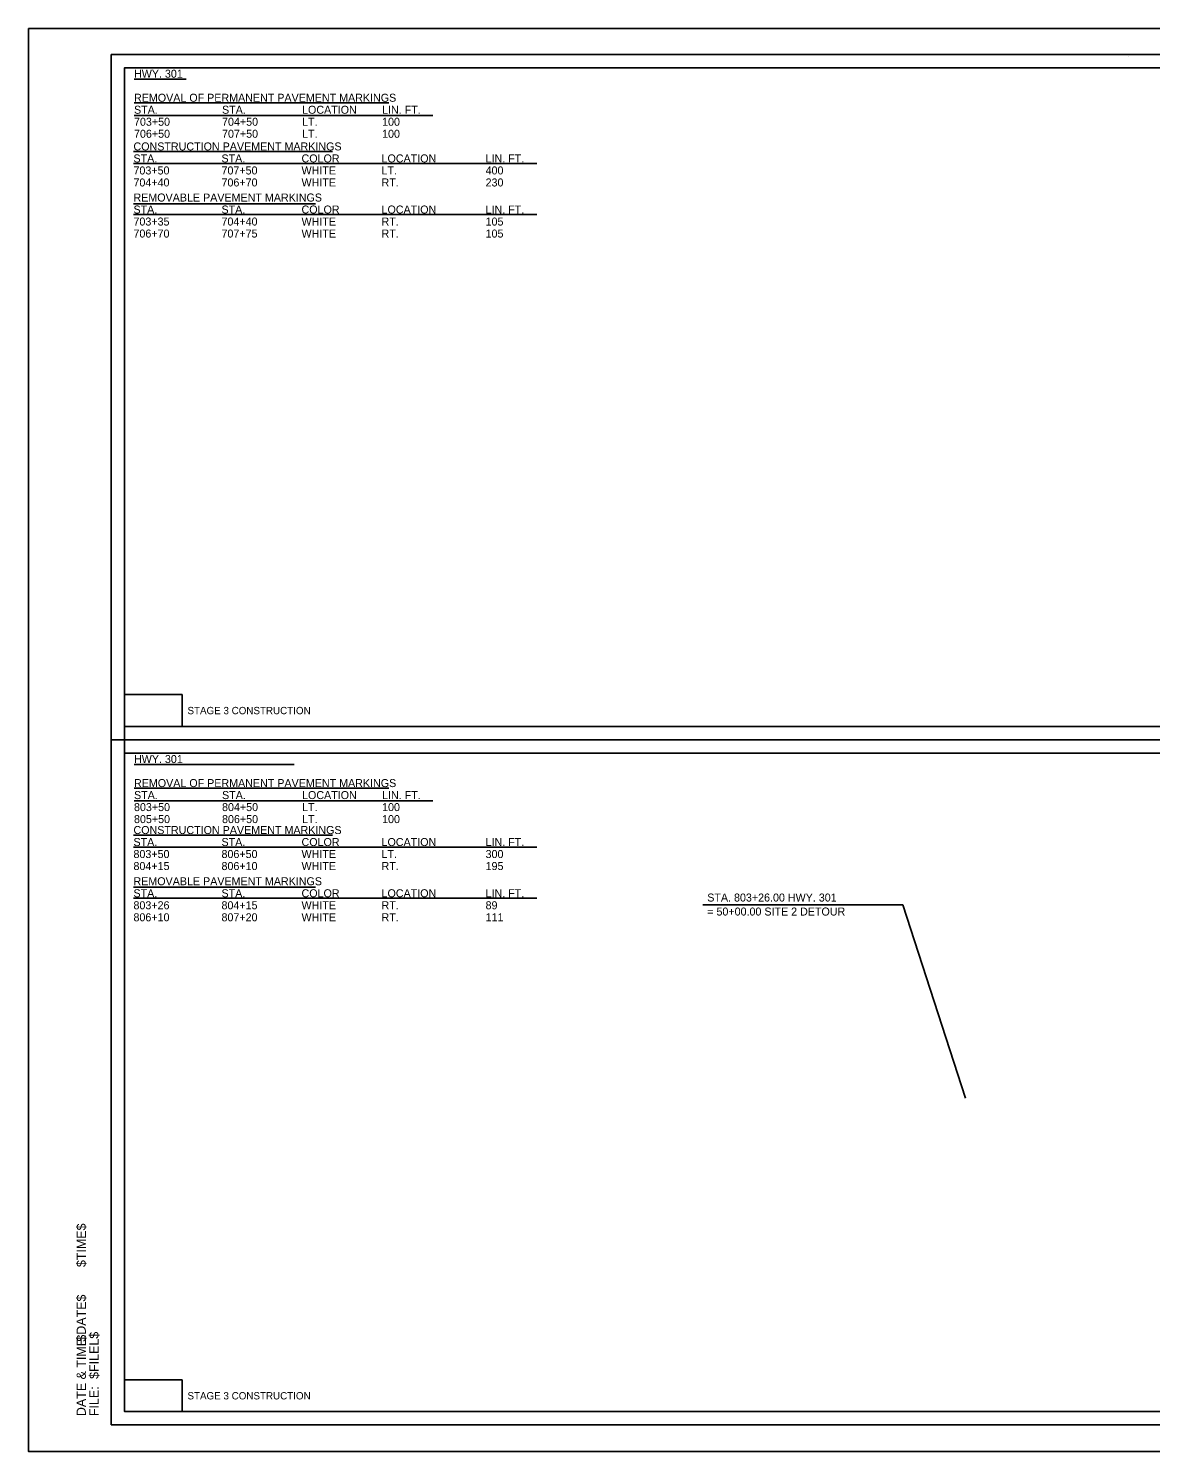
# Model space of a CAD drawing. Extents: x 1368648 to 1927880, y -1037443 to 380209.
# Drawn here: x 1377930 to 1378771, y 378686 to 379753 of the extents above; entities that cross this region are included whole.
import ezdxf

# ---------------------------------------------------------------- set-up
doc = ezdxf.new("R2010")
doc.units = 0
for name, color, linetype in [('Default', 7, 'Continuous'), ('R_Border', 7, 'Continuous'), ('R_Border Notes', 7, 'Continuous'), ('R_Detour Annot Limits', 7, 'Continuous'), ('R_No Plot', 7, 'Continuous')]:
    doc.layers.add(name, color=color, linetype=linetype)

msp = doc.modelspace()

# ---------------------------------------------------------------- linework, layer by layer
at = {"layer": 'Default'}
for p, q in [((1378009.2, 379714.7), (1378048.2, 379714.7)), ((1378009.2, 379696.9), (1378200.2, 379696.9)), ((1378009.2, 379687.5), (1378233.2, 379687.5)), ((1378008.9, 379660.4), (1378158, 379660.4)), ((1378008.9, 379651.4), (1378311.1, 379651.4)), ((1378008.9, 379621.4), (1378145.3, 379621.4)), ((1378008.9, 379613.2), (1378311.1, 379613.2)), ((1378009.2, 379201), (1378129.2, 379201)), ((1378009.2, 379183.2), (1378200.2, 379183.2)), ((1378009.2, 379173.9), (1378233.2, 379173.9)), ((1378008.9, 379148), (1378158, 379148)), ((1378008.9, 379139), (1378311.1, 379139)), ((1378008.9, 379109), (1378145.3, 379109)), ((1378008.9, 379100.8), (1378311.1, 379100.8))]:
    msp.add_line(p, q, dxfattribs=at)
for points in [[(1378002.1, 379229.6), (1378045.2, 379229.6), (1378045.2, 379253.4), (1378002.1, 379253.4), (1378002.1, 379229.6)], [(1378002.1, 378716), (1378045.2, 378716), (1378045.2, 378739.7), (1378002.1, 378739.7), (1378002.1, 378716)]]:
    msp.add_lwpolyline(points, dxfattribs=at)
at = {"layer": 'R_Border'}
for p, q in [((1377992.1, 379733.3), (1379573, 379733.3)), ((1377992.1, 378706), (1377992.1, 379733.3)), ((1378754.7, 379732), (1378754.7, 379732)), ((1378754.7, 379732), (1378754.7, 379732)), ((1379573, 379219.6), (1377992.1, 379219.6)), ((1377992.1, 378706), (1377992.1, 378706)), ((1379573, 378706), (1377992.1, 378706))]:
    msp.add_line(p, q, dxfattribs=at)
at = {"layer": 'R_Detour Annot Limits'}
msp.add_lwpolyline([(1378435.6, 379095.8), (1378585.6, 379095.8), (1378632.6, 378950.9)], dxfattribs=at)
at = {"layer": 'R_No Plot'}
for points in [[(1377930.1, 379752.7), (1379596.8, 379752.7), (1379596.8, 378686), (1377930.1, 378686)], [(1379563, 379229.6), (1378002.1, 379229.6), (1378002.1, 379723.3), (1379249.8, 379723.3), (1379249.8, 379673.9), (1379337.5, 379673.9), (1379458, 379673.9), (1379458, 379562.2), (1379563, 379562.2)], [(1379563, 379229.6), (1378002.1, 379229.6), (1378002.1, 379723.3), (1379249.8, 379723.3), (1379249.8, 379673.9), (1379337.5, 379673.9), (1379458, 379673.9), (1379458, 379562.2), (1379563, 379562.2)], [(1379563, 379229.6), (1378002.1, 379229.6), (1378002.1, 379723.3), (1379249.8, 379723.3), (1379249.8, 379673.9), (1379337.5, 379673.9), (1379458, 379673.9), (1379458, 379562.2), (1379563, 379562.2)], [(1379563, 379229.6), (1378002.1, 379229.6), (1378002.1, 379723.3), (1379249.8, 379723.3), (1379249.8, 379673.9), (1379337.5, 379673.9), (1379458, 379673.9), (1379458, 379562.2), (1379563, 379562.2)], [(1379563, 379229.6), (1378002.1, 379229.6), (1378002.1, 379723.3), (1379249.8, 379723.3), (1379249.8, 379673.9), (1379337.5, 379673.9), (1379458, 379673.9), (1379458, 379562.2), (1379563, 379562.2)], [(1379563, 379229.6), (1378002.1, 379229.6), (1378002.1, 379723.3), (1379249.8, 379723.3), (1379249.8, 379673.9), (1379337.5, 379673.9), (1379458, 379673.9), (1379458, 379562.2), (1379563, 379562.2)], [(1379563, 379229.6), (1378002.1, 379229.6), (1378002.1, 379723.3), (1379249.8, 379723.3), (1379249.8, 379673.9), (1379337.5, 379673.9), (1379458, 379673.9), (1379458, 379562.2), (1379563, 379562.2)], [(1378002.1, 379723.3), (1379249.8, 379723.3), (1379249.8, 379673.9), (1379337.5, 379673.9), (1379458, 379673.9), (1379458, 379562.2), (1379563, 379562.2), (1379563, 378716), (1378002.1, 378716)], [(1378002.1, 379209.6), (1379563, 379209.6), (1379563, 378716), (1378002.1, 378716)], [(1378002.1, 379209.6), (1379563, 379209.6), (1379563, 378716), (1378002.1, 378716)], [(1378002.1, 379209.6), (1379563, 379209.6), (1379563, 378716), (1378002.1, 378716)], [(1378002.1, 379209.6), (1379563, 379209.6), (1379563, 378716), (1378002.1, 378716)], [(1378002.1, 379209.6), (1379563, 379209.6), (1379563, 378716), (1378002.1, 378716)], [(1378002.1, 379209.6), (1379563, 379209.6), (1379563, 378716), (1378002.1, 378716)], [(1378002.1, 379209.6), (1379563, 379209.6), (1379563, 378716), (1378002.1, 378716)]]:
    msp.add_lwpolyline(points, close=True, dxfattribs=at)

# ---------------------------------------------------------------- texts
at = {"layer": 'Default'}
for s, height, p in [('HWY. 301 ', 6, (1378009.2, 379715.8)), ('REMOVAL OF PERMANENT PAVEMENT MARKINGS', 6, (1378009.2, 379697.8)), ('STA.', 6, (1378009.2, 379688.8)), ('STA.', 6, (1378075.2, 379688.8)), ('LOCATION', 6, (1378135.2, 379688.8)), ('LIN. FT.', 6, (1378195.2, 379688.8)), ('703+50 ', 6, (1378009.2, 379679.8)), ('704+50', 6, (1378075.2, 379679.8)), ('LT.', 6, (1378135.2, 379679.8)), ('100', 6, (1378195.2, 379679.8)), ('CONSTRUCTION PAVEMENT MARKINGS', 6, (1378008.8, 379661.3)), ('706+50', 6, (1378009.2, 379670.8)), ('707+50', 6, (1378075.2, 379670.8)), ('LT.', 6, (1378135.2, 379670.8)), ('100', 6, (1378195.2, 379670.8)), ('STA.', 6, (1378008.8, 379652.3)), ('STA.', 6, (1378074.8, 379652.3)), ('COLOR', 6, (1378134.8, 379652.3)), ('LOCATION', 6, (1378194.8, 379652.3)), ('LIN. FT.', 6, (1378272.8, 379652.3)), ('703+50', 6, (1378008.8, 379643.3)), ('707+50', 6, (1378074.8, 379643.3)), ('WHITE', 6, (1378134.8, 379643.3)), ('LT.', 6, (1378194.8, 379643.3)), ('400', 6, (1378272.8, 379643.3)), ('704+40', 6, (1378008.8, 379634.3)), ('706+70', 6, (1378074.8, 379634.3)), ('WHITE', 6, (1378134.8, 379634.3)), ('RT.', 6, (1378194.8, 379634.3)), ('230', 6, (1378272.8, 379634.3)), ('REMOVABLE PAVEMENT MARKINGS', 6, (1378008.8, 379623)), ('STA.', 6, (1378008.8, 379614)), ('STA.', 6, (1378074.8, 379614)), ('COLOR', 6, (1378134.8, 379614)), ('LOCATION', 6, (1378194.8, 379614)), ('LIN. FT.', 6, (1378272.8, 379614)), ('703+35', 6, (1378008.8, 379605)), ('704+40', 6, (1378074.8, 379605)), ('WHITE', 6, (1378134.8, 379605)), ('RT.', 6, (1378194.8, 379605)), ('105', 6, (1378272.8, 379605)), ('706+70', 6, (1378008.8, 379596)), ('707+75', 6, (1378074.8, 379596)), ('WHITE', 6, (1378134.8, 379596)), ('RT.', 6, (1378194.8, 379596)), ('105', 6, (1378272.8, 379596)), ('  STAGE 3 CONSTRUCTION', 5.5, (1378045.2, 379238.7)), ('HWY. 301 ', 6, (1378009.2, 379202.1)), ('REMOVAL OF PERMANENT PAVEMENT MARKINGS', 6, (1378009.2, 379184.1)), ('STA.', 6, (1378009.2, 379175.1)), ('STA.', 6, (1378075.2, 379175.1)), ('LOCATION', 6, (1378135.2, 379175.1)), ('LIN. FT.', 6, (1378195.2, 379175.1)), ('803+50 ', 6, (1378009.2, 379166.1)), ('804+50', 6, (1378075.2, 379166.1)), ('LT.', 6, (1378135.2, 379166.1)), ('100', 6, (1378195.2, 379166.1)), ('CONSTRUCTION PAVEMENT MARKINGS', 6, (1378008.8, 379148.9)), ('805+50', 6, (1378009.2, 379157.1)), ('806+50', 6, (1378075.2, 379157.1)), ('LT.', 6, (1378135.2, 379157.1)), ('100', 6, (1378195.2, 379157.1)), ('STA.', 6, (1378008.8, 379139.9)), ('STA.', 6, (1378074.8, 379139.9)), ('COLOR', 6, (1378134.8, 379139.9)), ('LOCATION', 6, (1378194.8, 379139.9)), ('LIN. FT.', 6, (1378272.8, 379139.9)), ('803+50', 6, (1378008.8, 379130.9)), ('806+50', 6, (1378074.8, 379130.9)), ('WHITE', 6, (1378134.8, 379130.9)), ('LT.', 6, (1378194.8, 379130.9)), ('300', 6, (1378272.8, 379130.9)), ('804+15', 6, (1378008.8, 379121.9)), ('806+10', 6, (1378074.8, 379121.9)), ('WHITE', 6, (1378134.8, 379121.9)), ('RT.', 6, (1378194.8, 379121.9)), ('195', 6, (1378272.8, 379121.9)), ('REMOVABLE PAVEMENT MARKINGS', 6, (1378008.8, 379110.5)), ('STA.', 6, (1378008.8, 379101.5)), ('STA.', 6, (1378074.8, 379101.5)), ('COLOR', 6, (1378134.8, 379101.5)), ('LOCATION', 6, (1378194.8, 379101.5)), ('LIN. FT.', 6, (1378272.8, 379101.5)), ('803+26', 6, (1378008.8, 379092.5)), ('804+15', 6, (1378074.8, 379092.5)), ('WHITE', 6, (1378134.8, 379092.5)), ('RT.', 6, (1378194.8, 379092.5)), ('89', 6, (1378272.8, 379092.5)), ('806+10', 6, (1378008.8, 379083.5)), ('807+20', 6, (1378074.8, 379083.5)), ('WHITE', 6, (1378134.8, 379083.5)), ('RT.', 6, (1378194.8, 379083.5)), ('111', 6, (1378272.8, 379083.5)), ('  STAGE 3 CONSTRUCTION', 5.5, (1378045.2, 378725.1))]:
    msp.add_text(s, height=height, dxfattribs=at).set_placement(p)
at = {"layer": 'R_Border Notes'}
for s, height, p in [('$TIME$', 6.98, (1377973.1, 378824.3)), ('$DATE$', 6.98, (1377973.1, 378768.4)), ('DATE & TIME:', 6.984, (1377973.1, 378712.6)), ('$FILEL$', 6.98, (1377982.7, 378740.5)), ('FILE: ', 6.98, (1377982.7, 378712.6))]:
    msp.add_text(s, height=height, rotation=90, dxfattribs=at).set_placement(p)
at = {"layer": 'R_Detour Annot Limits'}
for s, p in [('STA. 803+26.00 HWY. 301', (1378439, 379098.3)), ('= 50+00.00 SITE 2 DETOUR', (1378439, 379087.8))]:
    msp.add_text(s, height=6, rotation=0.0001, dxfattribs=at).set_placement(p)

doc.saveas('drawing.dxf')
